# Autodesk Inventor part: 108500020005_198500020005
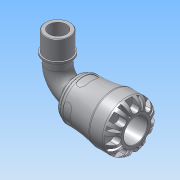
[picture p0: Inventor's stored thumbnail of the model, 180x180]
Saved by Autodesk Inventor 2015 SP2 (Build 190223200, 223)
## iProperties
Created: 2016-12
Part Number: 108500020005_198500020005
Material: PVC-Piping
Description: PLASSON 90° ELBOW WITH THREADED MALE OFFTAKE 20X1/2" SERIES 1
Document SubType Name: Modeling
Designer: KIM
Mass: 664.223 g
Surface Area: 733.008 cm^2
Volume: 474.445 cm^3
Density: 1.4 g/cm^3
Appearance: Smooth - White
Author: KIM
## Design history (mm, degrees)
derived "1085.ipt"
feature "Solid1::1085.ipt"
tag "TaggingFeature1"
body "Solid1"
other parameters: "d1" = 18.9, "d3" = 25, "d4" = 41, "d8" = 34.85, "d13" = 6.4, "d14" = 6.4, "d15" = 0, "d17" = 360 deg, "d19" = 8 deg, "d20" = 0.4, "d21" = 0.4, "d22" = 8 deg, "d24" = 0, "d26" = 360 deg, "d33" = 4.1, "d43" = 31.98, "d51" = 0.41, "d54" = 7, "d55" = 4.4, "d57" = 12.544, "d58" = 0, "d74" = 0, "d78" = 45, "d82" = 0.4, "d115" = 360 deg, "d207" = 90 deg, "d228" = 5.95, "d247" = 0.82, "d248" = 2.7, "d268" = 19.1675, "d269" = 2.7, "d270" = 66, "d276" = 20.955, "d277" = 16, "d278" = 23.0505, "d279" = 41, "d280" = 17.6, "d281" = 3.14325, "d283" = 18.8595, "d286" = 0, "d287" = 0, "d288" = 14.6685, "d290" = 6.56025, "d292" = 30 deg, "E_" = 41, "l_" = 45, "A_" = 66, "A_1" = 41, "l_2" = 16, "R_" = 20.955, "d9" = 8, "d11" = 41, "d12" = 25, "d289" = 14.6685
